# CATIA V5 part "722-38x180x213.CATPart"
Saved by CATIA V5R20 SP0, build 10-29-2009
Part number: 722-38x180x213
Definition: NONE
Nomenclature: 722-38x180x213
Source: Unknown
Description: 722-38x180x213
Bounding box of the stored display mesh (mm): x -19 to 19, y -19 to 19, z -165 to 48
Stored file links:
  C:\Users\Utente\Desktop\IO LAVORO\3D X SITO CF\X SITO\722\722-38x180x213.CATPart

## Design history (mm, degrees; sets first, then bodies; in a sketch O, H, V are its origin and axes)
Body1 "722-38x180x213" (main body)
  Solid1: solid without history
